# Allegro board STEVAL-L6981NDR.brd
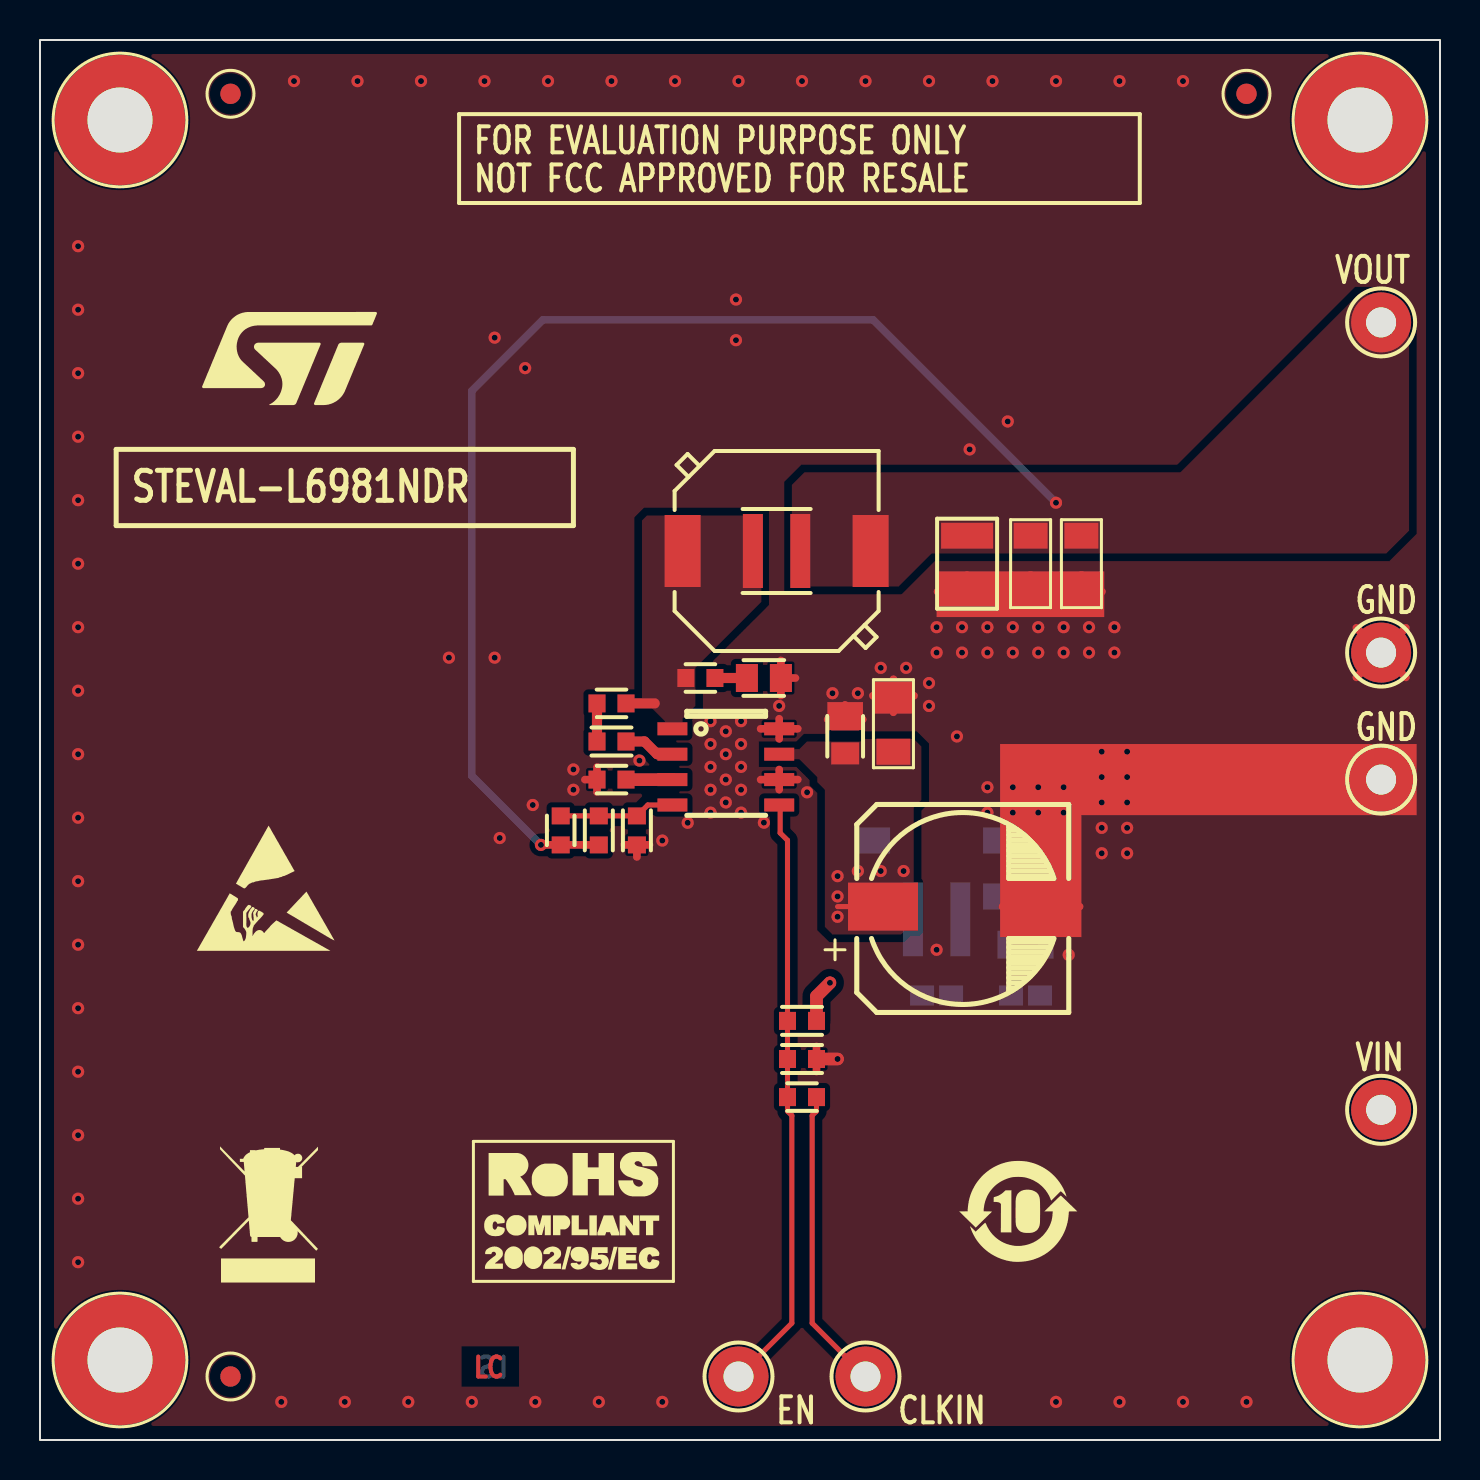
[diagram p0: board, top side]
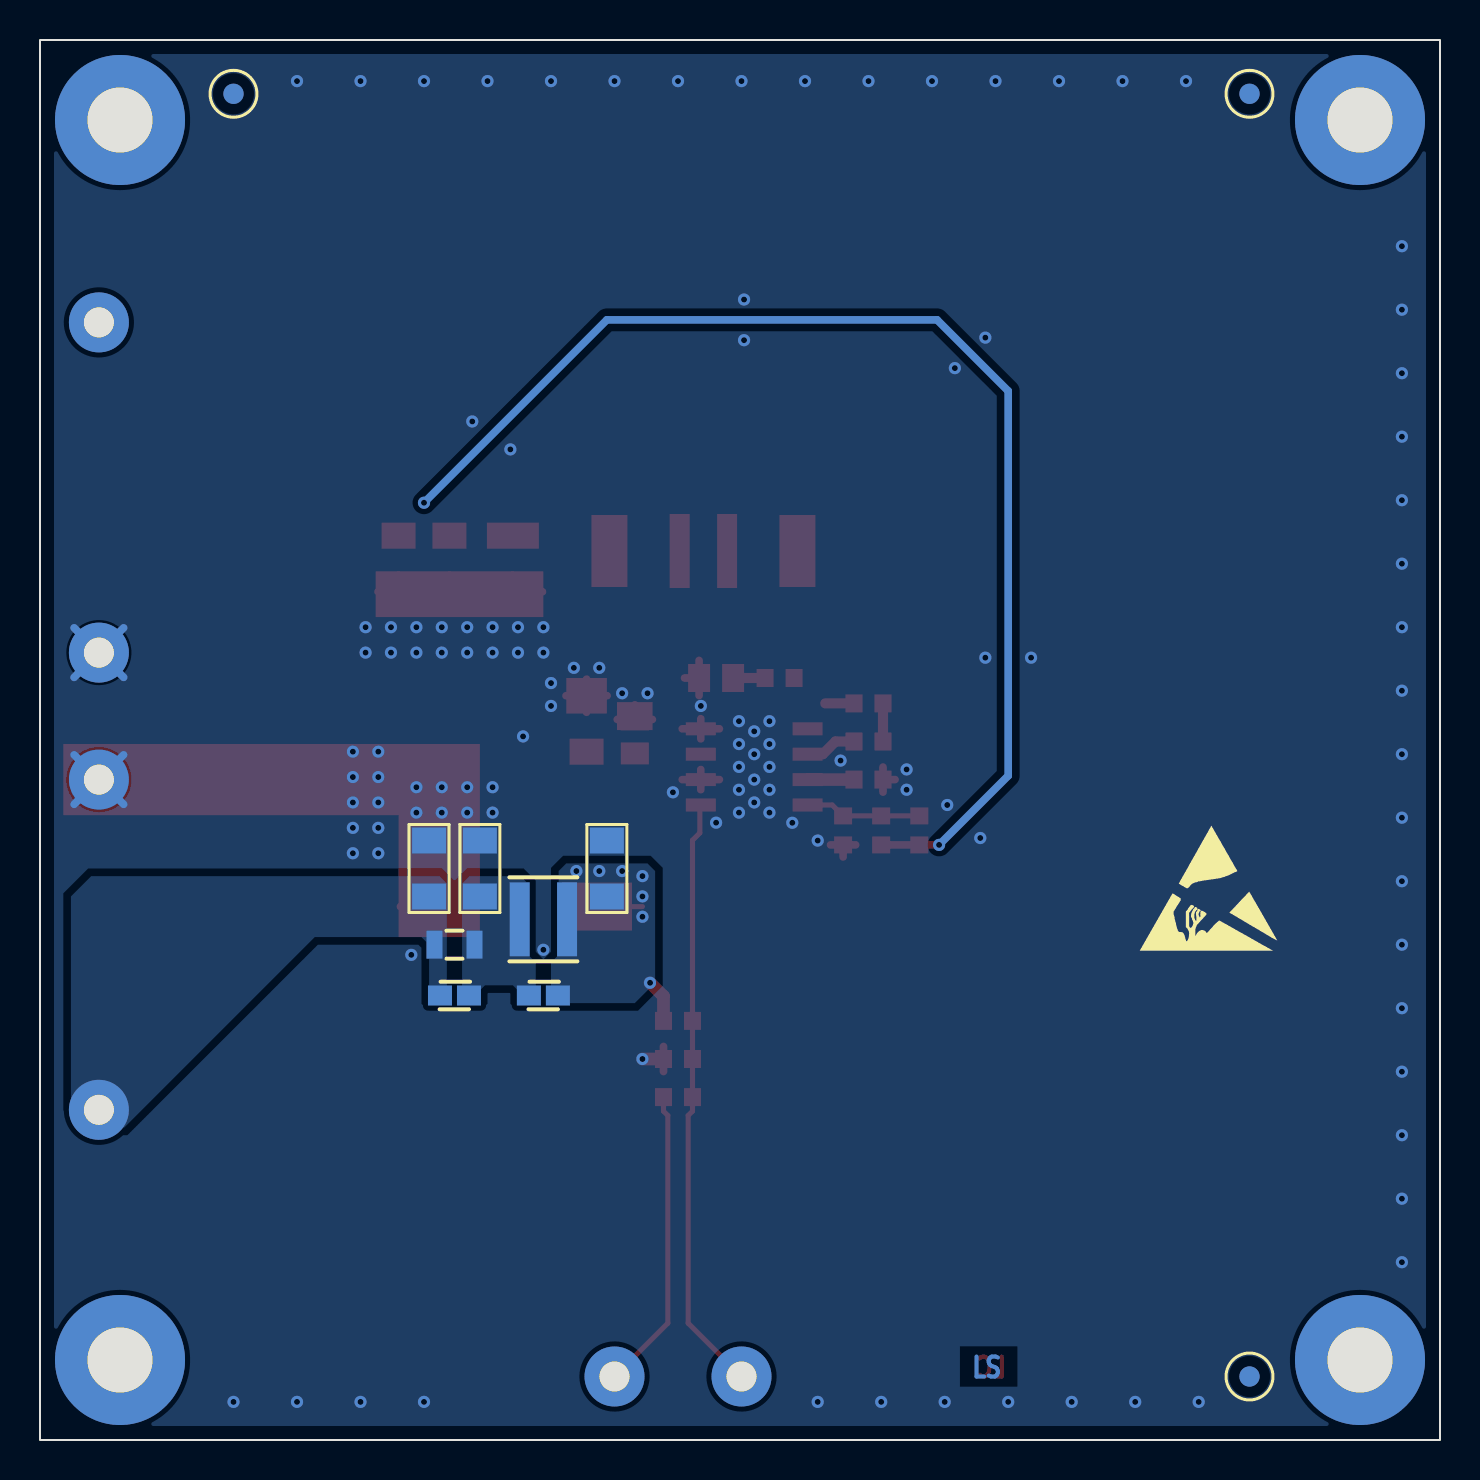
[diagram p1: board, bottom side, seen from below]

Outline 70 x 70 mm; copper layers: TOP, BOTTOM. Coordinates in mm from the lower left corner of the outline.
Outline path: rectangle 0,0 70,70

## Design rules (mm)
constraint set DEFAULT: min track width 0.254
net group EN: nets EN N4101471 N4101491 N4114079 VIN_L6981
net group N00332: nets N00332 N00369 N00459 N00863 N01548 N4112988

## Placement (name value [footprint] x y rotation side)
C1  10uF  [C1206]  42.67 35.81 270 top
C2  1uF  [C0805]  40.26 35.18 270 top
C3  1uF 10V  [C0603]  28.57 33.02 0 top
C4  22uF  [C1210]  46.35 43.81 90 top
C5  n.m.  [C1206]  49.53 43.81 90 top
C6  n.m.  [C1206]  52.07 43.81 90 top
C7  100nF  [C0603]  28.57 36.83 0 top
C8  n.m.  [C0603]  26.04 30.48 90 top
C9  n.m.  [C0603]  38.1 17.14 0 top
C10  100uF  [EL_SMD_ALL_G]  46.1 26.67 0 top
C11  4.7uF  [C1206]  50.55 28.57 270 bottom
C12  4.7uF  [C1206]  48.01 28.57 270 bottom
C13  n.m.  [C0603]  33.02 38.1 180 top
C14  4.7uF  [C1206]  41.66 28.57 270 bottom
J1  CUT 3  [PONT2_0603_NO_PASTE]  49.28 22.23 180 bottom
J2  CUT 3  [PONT2_0603_NO_PASTE]  44.83 22.23 180 bottom
L1  33uH  [IND_MSS1038]  36.83 44.45 0 top
L2  n.m.  [IND_XAL4040]  36.83 44.45 0 top
L3  MPZ2012S221A  [IND_MPZ2012]  49.28 24.77 180 bottom
L4  4.7uH  [IND_XAL4040]  44.83 26.04 180 bottom
NOREF  -  []  5.08 -129.77 90 top
NOREF#2  -  []  151.12 -129.77 0 top
NOREF#3  -  []  261.75 -28.96 0 top
NOREF#4  -  []  26.67 11.43 0 top
NOREF#5  -  []  99.52 -134.87 0 top
NOREF#6  -  [unnamed#2]  9.53 67.31 0 top
NOREF#7  -  []  175.22 -133.59 0 top
NOREF#8  -  []  0.08 -86.59 90 top
NOREF#9  -  []  0.08 -40.41 90 top
NOREF#10  -  [unnamed#2]  9.53 3.17 0 top
NOREF#11  -  []  5.08 -37.41 90 top
NOREF#12  -  []  -4.83 14.73 0 top
NOREF#13  -  []  50.85 -134.87 0 top
NOREF#14  -  []  48.9 11.43 0 top
NOREF#15  -  []  5.14 -129.77 0 top
NOREF#16  -  []  265.3 -17.78 0 top
NOREF#17  -  [unnamed#3]  4 4 0 top
NOREF#18  -  []  0 -134.87 0 top
NOREF#19  -  []  0.08 5.77 90 top
NOREF#20  -  []  5.08 8.76 90 top
NOREF#21  -  []  0 -134.87 90 top
NOREF#22  -  []  11.43 26.67 0 top
NOREF#23  -  []  27.94 54.48 0 top
NOREF#24  -  [unnamed#3]  4 66 0 top
NOREF#25  -  []  0.64 51.94 90 top
NOREF#26  -  []  0.08 5.77 90 top
NOREF#27  -  []  5.08 -83.59 90 top
NOREF#28  -  []  148.18 -134.87 0 top
NOREF#29  -  []  102.48 -129.77 0 top
NOREF#30  -  []  0 70 0 top
NOREF#31  -  [unnamed#2]  60.33 67.31 0 top
NOREF#32  -  []  11.43 12.06 0 top
NOREF#33  -  []  8.89 54.48 0 top
NOREF#34  -  []  0 0 90 top
NOREF#35  -  []  196.98 -134.87 0 top
NOREF#36  -  []  174.14 54.46 0 top
NOREF#37  -  []  264.29 -17.78 0 top
NOREF#38  -  [unnamed#3]  66 66 0 top
NOREF#39  -  [unnamed#3]  66 4 0 top
NOREF#40  -  []  0.08 -132.77 90 top
NOREF#41  -  []  196.82 -134.87 0 top
NOREF#42  -  []  0.05 51.94 90 top
NOREF#43  -  []  12.7 53.98 0 top
NOREF#44  -  []  0.08 -132.77 90 top
NOREF#45  -  []  53.81 -129.77 0 top
NOREF#46  -  [unnamed#2]  9.53 3.17 180 bottom
NOREF#47  -  []  11.43 26.67 180 bottom
NOREF#48  -  [unnamed#2]  60.33 67.31 180 bottom
NOREF#49  -  [unnamed#2]  9.53 67.31 180 bottom
R1  0 Ohm  [0603]  28.57 34.92 0 top
R2  400K  [0603]  27.94 30.48 90 top
R3  82K  [0603]  29.84 30.48 270 top
R4  10k  [0603]  38.1 20.95 0 top
R5  n.m.  [0603]  38.1 19.05 180 top
R6  n.m.  [0805]  36.2 38.1 0 top
TP1  EN  [TP_TORRETTA_13MM_F1_5]  34.92 3.17 90 top
TP2  CLK_IN  [TP_TORRETTA_13MM_F1_5]  41.27 3.17 90 top
TP3  VIN  [TP_TORRETTA_13MM_F1_5]  67.06 16.51 0 top
TP4  GND  [TP_TORRETTA_13MM_F1_5]  67.06 33.02 0 top
TP5  GND  [TP_TORRETTA_13MM_F1_5]  67.06 39.37 90 top
TP6  VOUT  [TP_TORRETTA_13MM_F1_5]  67.06 55.88 0 top
U1  L6981  [SO8]  34.29 33.66 0 top

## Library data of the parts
C1-C9 C11-C14 = C
C10 = CAPACITOR POL_1
J1 J2 = CUT 3_16
L1-L4 = L
R1-R6 = R
TP1-TP6 = TP
U1 = L6981

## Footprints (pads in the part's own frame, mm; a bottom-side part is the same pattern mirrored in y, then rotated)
0603
  rect 0.85x0.9 smd: 1(-0.725,0) 2(0.725,0)
0805
  rect 1.1x1.4 smd: 1(-0.85,0) 2(0.85,0)
C0603
  rect 0.85x0.9 smd: 1(-0.725,0) 2(0.725,0)
C0805
  rect 1.1x1.4 smd: 1(-0.85,0) 2(0.85,0)
C1206
  rect 1.3x1.7 smd: 1(-1.4,0) 2(1.4,0)
C1210
  rect 1.3x2.6 smd: 1(-1.4,0) 2(1.4,0)
EL_SMD_ALL_G
  rect 3.5x2.4 smd: 1(-3.95,0) 2(3.95,0)
IND_MPZ2012
  rect 0.8x1.4 smd: 1(-1,0) 2(1,0)
IND_MSS1038
  rect 1.8x3.6 smd: 1(-4.7,0) 2(4.7,0)
IND_XAL4040
  rect 1x3.7 smd: 1(-1.185,0) 2(1.185,0)
PONT2_0603_NO_PASTE
  rect 1.2x1 smd: 1(-0.725,0) 2(0.725,0)
SO8
  rect 1.5x0.65 smd: 1(-2.67,1.905) 2(-2.67,0.635) 3(-2.67,-0.635) 4(-2.67,-1.905) 5(2.67,-1.905) 6(2.67,-0.635) 7(2.67,0.635) 8(2.67,1.905)
TP_TORRETTA_13MM_F1_5
  round 3 hole 1.5: 1(0,0)
unnamed#2
  round 1.016 smd: (0,0)
unnamed#3
  round 6.502 hole 3.25: 1(0,0)

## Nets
GND_POWER: C1.1 C2.1 C3.1 C4.1 C5.1 C6.1 C10.2 C11.1 C12.1 C14.1 R3.2 R5.1 R6.2 TP4.1 TP5.1 U1.6 U1.8
VIN_L6981: C1.2 C2.2 C10.1 C14.2 J2.2 L4.2 R4.2 U1.7(\VIN\)
EN: C9.1 R4.1 R5.2 TP1.1 U1.5
N00332: C7.2 C13.2 L1.1 L2.1 U1.1
N00369: R1.2 U1.2
N00459: C7.1 R1.1
N00575: C3.2 U1.3
N00863: C4.2 C5.2 C6.2 C8.1 L1.2 L2.2 R2.1 TP6.1
N01548: C8.2 R2.2 R3.1 U1.4
N4101471: C12.2 J1.2 J2.1 L3.2 L4.1
N4101491: C11.2 J1.1 L3.1 TP3.1
N4112988: C13.1 R6.1
N4114079: C9.2 TP2.1

Pads without a net: NOREF#17 1; NOREF#24 1; NOREF#38 1; NOREF#39 1

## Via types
v1: diameter 0.61, hole 0.3, TOP to BOTTOM, 128 vias

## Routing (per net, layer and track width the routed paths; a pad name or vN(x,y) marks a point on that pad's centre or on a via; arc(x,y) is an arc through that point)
GND_POWER: length 67.1
  TOP w0.381: C10.2 51.98,26.67 ; C10.2 50.05,25.29 ; C10.2 48.12,26.67 ; C10.2 50.05,28.05 ; C6.1 52.07,43.24 ; C6.1 53.1,42.41 ; C6.1 51.04,42.41 ; C6.1 52.07,41.59 ; 29.22,29.75 R3.2 ; R3.2 29.84,29.15 ; R3.2 30.47,29.75 ; 48.5,42.41 C5.1 ; C5.1 49.53,43.24 ; C5.1 49.53,41.59 ; C5.1 50.56,42.41 ; 65.82,34.26 TP4.1 ; TP4.1 68.29,31.78 ; TP4.1 68.29,34.26 ; TP4.1 65.82,31.78 ; C2.1 41.14,36.03 ; C2.1 39.38,36.03 ; C2.1 40.26,36.76 ; 38.83,19.68 R5.1 38.83,18.42 ; R6.2 37.77,38.1 ; R6.2 37.05,37.22 ; R6.2 37.05,38.98 ; U1.6 37.89,33.02 ; U1.6 36.03,33.02 ; U1.6 36.96,32.52 ; U1.6 36.96,33.52 ; 27.25,33.02 C3.1 ; C3.1 27.85,33.65 ; C3.1 27.85,32.39 ; C1.1 42.67,38.04 ; C1.1 43.7,37.21 ; C1.1 41.64,37.21 ; C1.1 42.67,36.39 ; 44.88,42.41 C4.1 ; C4.1 46.35,43.24 ; C4.1 47.83,42.41 ; C4.1 46.35,41.59 ; TP5.1 68.29,38.13 ; TP5.1 65.82,40.61 ; TP5.1 65.82,38.13 ; TP5.1 68.29,40.61 ; U1.8 37.89,35.56 ; U1.8 36.96,36.06 ; U1.8 36.03,35.56 ; U1.8 36.96,35.06
  TOP w0.635: R5.1 v1(39.88,19.05)
  BOTTOM w0.381: 65.82,31.78 TP4.1 ; TP4.1 68.29,31.78 ; TP4.1 65.82,34.26 ; TP4.1 68.29,34.26 ; TP5.1 68.29,40.61 ; TP5.1 68.29,38.13 ; TP5.1 65.82,40.61 ; TP5.1 65.82,38.13
  vias: v1(1.91,59.69) v1(1.91,56.52) v1(1.91,53.34) v1(1.91,50.16) v1(1.91,46.99) v1(1.91,43.81) v1(1.91,40.64) v1(1.91,37.47) v1(1.91,34.29) v1(1.91,31.11) v1(1.91,27.94) v1(1.91,24.77) v1(1.91,21.59) v1(1.91,18.41) v1(1.91,15.24) v1(1.91,12.06) v1(1.91,8.89) v1(12.06,1.91) v1(12.7,67.94) v1(15.24,1.91) v1(15.88,67.94) v1(18.41,1.91) v1(19.05,67.94) v1(20.45,39.12) v1(21.59,1.91) v1(22.23,67.94) v1(22.73,55.12) v1(22.73,39.12) v1(22.99,30.1) v1(24.26,53.59) v1(24.64,31.75) v1(24.77,1.91) v1(25.4,67.94) v1(26.67,33.53) v1(26.67,32.51) v1(27.94,1.91) v1(28.57,67.94) v1(29.97,33.97) v1(31.11,29.97) v1(31.11,1.91) v1(31.75,67.94) v1(32.38,30.86) v1(33.53,35.94) v1(33.53,34.8) v1(33.53,33.66) v1(33.53,32.51) v1(33.53,31.37) v1(34.29,35.43) v1(34.29,34.29) v1(34.29,33.02) v1(34.29,31.88) v1(34.8,57.02) v1(34.8,54.99) v1(34.92,67.94) v1(35.05,35.94) v1(35.05,34.8) v1(35.05,33.66) v1(35.05,32.51) v1(35.05,31.37) v1(36.2,30.87) v1(36.96,36.7) v1(38.1,67.94) v1(38.35,32.38) v1(39.62,37.34) v1(40.89,37.34) v1(41.27,67.94) v1(42.04,38.61) v1(43.31,38.61) v1(44.45,67.94) v1(44.45,37.85) v1(44.45,36.7) v1(44.83,40.64) v1(44.83,39.37) v1(44.83,24.51) v1(45.85,35.18) v1(46.1,40.64) v1(46.1,39.37) v1(46.48,49.53) v1(47.37,40.64) v1(47.37,39.37) v1(47.37,32.64) v1(47.37,31.37) v1(47.62,67.94) v1(48.39,50.93) v1(48.64,40.64) v1(48.64,39.37) v1(48.64,32.64) v1(48.64,31.37) v1(49.91,40.64) v1(49.91,39.37) v1(49.91,32.64) v1(49.91,31.37) v1(50.8,67.94) v1(50.8,1.91) v1(51.18,40.64) v1(51.18,39.37) v1(51.18,32.64) v1(51.18,31.37) v1(51.44,24.26) v1(52.45,40.64) v1(52.45,39.37) v1(53.09,34.42) v1(53.09,33.15) v1(53.09,31.88) v1(53.09,30.61) v1(53.09,29.34) v1(53.72,40.64) v1(53.72,39.37) v1(53.98,67.94) v1(53.98,1.91) v1(54.36,34.42) v1(54.36,33.15) v1(54.36,31.88) v1(54.36,30.61) v1(54.36,29.34) v1(57.15,67.94) v1(57.15,1.91) v1(60.33,1.91)
VIN_L6981: length 3.6
  TOP w0.254: 41.26,26.67 39.88,26.67
  TOP w0.635: v1(39.5,22.86) 38.83,22.19 R4.2
  vias: v1(39.88,28.19) v1(39.88,27.18) v1(39.88,26.16) v1(40.89,28.45) v1(42.04,28.45) v1(43.18,28.45)
EN: length 29.9
  TOP w0.254: TP1.1 37.59,5.84 37.59,16.22 37.38,16.44 C9.1 R5.2 R4.1 37.38,29.99 37.01,30.35 37.01,31.7 U1.5
N00332: length 1.4
  TOP w0.508: C7.2 30.73,36.83
N00369: length 2.6
  TOP w0.508: U1.2 30.86,34.29 30.23,34.92 R1.2
N00459: length 1.9
  TOP w0.508: R1.1 C7.1
N00575: length 2.3
  TOP w0.635: U1.3 C3.2
N00863: length 61.5
  TOP w0.381: v1(25.05,29.75) C8.1 R2.1
  BOTTOM w0.381: v1(25.05,29.75) 21.59,33.21 21.59,52.45 25.15,56.01 41.66,56.01 v1(50.8,46.86)
N01548: length 5.8
  TOP w0.254: U1.4 30.39,31.75 29.84,31.2 26.04,31.2
N4112988: length 1.6
  TOP w0.508: 33.74,38.1 R6.1
N4114079: length 15.2
  TOP w0.254: TP2.1 38.61,5.84 38.61,16.22 38.83,16.44 C9.2

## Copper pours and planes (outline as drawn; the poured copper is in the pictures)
GND_POWER on TOP (solid shape): 41.15,35.5 39.37,35.5 39.37,36.89 41.15,36.89
GND_POWER on TOP (solid shape): 43.69,36.32 41.66,36.32 41.66,38.1 43.69,38.1
GND_POWER on TOP (solid shape): 53.21,41.15 44.83,41.15 44.83,43.43 53.21,43.43
GND_POWER on TOP (solid shape): 68.83,31.24 52.07,31.24 52.07,25.15 48.01,25.15 48.01,34.8 68.83,34.8
GND_POWER on TOP: 0.7,0.7 0.7,69.3 69.3,69.3 69.3,0.7
GND_POWER on BOTTOM: 0.7,69.3 69.3,69.3 69.3,0.7 0.7,0.7
VIN_L6981 on TOP: 39.62,25.27 39.24,25.65 39.24,32.51 38.86,32.89 38.86,33.15 37.97,34.04 36.32,34.04 36.32,34.54 37.97,34.54 38.35,34.92 41.02,34.92 41.15,35.05 43.69,35.05 44.07,34.67 44.07,32 43.69,31.62 43.69,25.91 43.05,25.27
VIN_L6981 on BOTTOM: 39.24,22.86 40.26,21.84 44.32,21.84 44.45,21.97 44.45,23.88 44.07,24.26 44.07,28.45 43.69,28.83 39.62,28.83 39.24,28.45
N00332 on TOP: 30.1,37.08 31.24,35.94 31.24,35.43 32.13,35.43 32.13,36.07 32.77,36.7 32.77,38.61 36.07,41.91 36.07,46.23 30.35,46.23 30.1,45.97
N00863 on TOP: 44.58,44.32 42.93,42.67 37.59,42.67 37.59,47.75 38.23,48.39 57.02,48.39 65.91,57.28 67.06,57.28 68.45,55.88 68.45,45.47 67.31,44.32
N4101471 on BOTTOM: 48.9,27.81 48.9,21.97 48.77,21.84 48.13,21.84 48.01,21.97 48.01,22.48 47.75,22.73 46.35,22.73 46.1,22.48 46.1,21.97 45.97,21.84 45.34,21.84 45.21,21.97 45.21,23.88 45.59,24.26 45.59,27.81 45.97,28.19 48.51,28.19
N4101491 on BOTTOM: 49.66,27.81 49.66,21.97 49.78,21.84 50.42,21.84 50.55,21.97 50.55,24.77 50.93,25.15 56.26,25.15 65.79,15.62 67.44,15.62 68.45,16.64 68.45,27.18 67.44,28.19 50.04,28.19

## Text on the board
BOTTOM: LS
Ref Des/Assembly Bottom: PIANO DI MONTAGGIO LATO SALDATURE
Package Geometry/Pastemask Bottom: PASTA SALDA LATO SALDATURE
Ref Des/Silkscreen Bottom: SERIGRAFIA LATO SALDATURE
User.Comments: SOLDER MASK LATO COMPONENTI | SOLDER MASK LATO SALDATURA
TOP: LC
Ref Des/Assembly Top: PIANO DI MONTAGGIO LATO COMPONENTI
Package Geometry/Pastemask Top: PASTA SALDA LATO COMPONENTI
Ref Des/Silkscreen Top: FOR EVALUATION PURPOSE ONLY | NOT FCC APPROVED FOR RESALE | EN | CLKIN | VOUT | GND | VIN | STEVAL-L6981NDR
BODY_CENTER: COPPER AREA ON OPPOSITE SIDE | 180 MILS | ENGRAVE TROUGH DISK CUTTER | +0.05mm | -0.05mm | +20 | -20 | PUT FOUR FIDUCIAL MARKS ON COMPONENTS SIDE | PUT A COPPER AREA ON SOLDER SIDE BELOW THE FID. MARK | cu DIAMETER 60 MILS | Solder mask opening 137 mils | SCHEDA1 | SCHEDA5 | SCHEDA9 | SCHEDA13 | SCHEDA2 | SCHEDA6 | SCHEDA10 | SCHEDA14 | SCHEDA3 | SCHEDA7 | SCHEDA11 | SCHEDA15 | SCHEDA4 | SCHEDA8 | SCHEDA12 | IFARCAD SNC | 24/06/11 | ST1CC40 SO8 | PANNELLO | ST1CC40S08 | 1.0
User.13: FIGURE | FINISHED_SIZE | 0.3 | 1.5 | 3.25 | DRILL CHART: TOP to BOTTOM | ALL UNITS ARE IN MILLIMETERS | PLATED | QTY | 128 | 6 | 4
